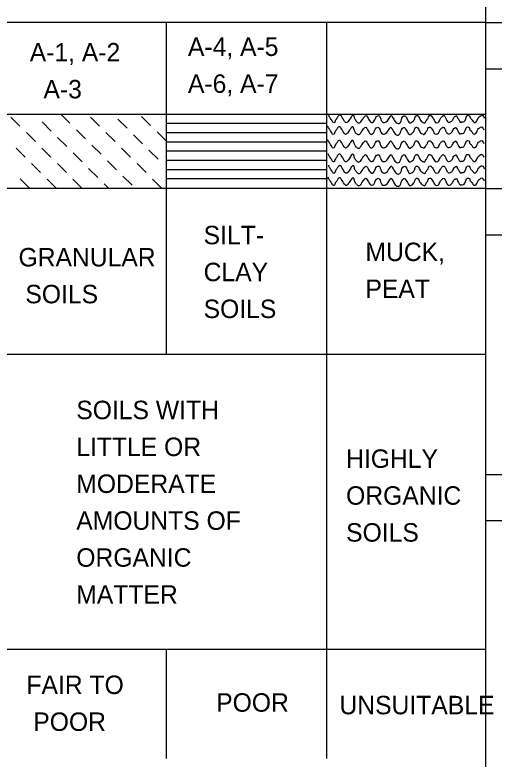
# Model space of a CAD drawing. Extents: x 278710 to 279187, y 171464 to 171625.
# Drawn here: x 279032.01 to 279043.27, y 171537.43 to 171554.93 of the extents above; entities that cross this region are included whole.
import ezdxf

# ---------------------------------------------------------------- set-up
doc = ezdxf.new("R2010")
doc.units = 0
doc.layers.add('Prop Strc Sect_ Misc - User Comment (Tx - small)', color=7, linetype='Continuous')

msp = doc.modelspace()

# ---------------------------------------------------------------- linework, layer by layer
at = {"layer": 'Prop Strc Sect_ Misc - User Comment (Tx - small)'}
for p, q in [((279043.07, 171566.02), (279043.07, 171485.806)), ((279005.33, 171554.763), (279043.07, 171554.763)), ((279035.566, 171546.942), (279035.566, 171554.737)), ((279039.34, 171537.446), (279039.34, 171554.763)), ((279081.678, 171554.741), (279043.07, 171554.741)), ((279081.678, 171553.657), (279043.07, 171553.657)), ((279005.33, 171552.594), (279043.07, 171552.594)), ((279032.125, 171552.316), (279031.913, 171552.529)), ((279033.089, 171552.594), (279033.301, 171552.382)), ((279033.995, 171552.316), (279033.783, 171552.529)), ((279034.429, 171552.477), (279034.642, 171552.264)), ((279035.197, 171552.329), (279034.984, 171552.542)), ((279032.859, 171552.199), (279032.646, 171552.412)), ((279035.566, 171552.382), (279039.34, 171552.382)), ((279039.366, 171552.312), (279039.361, 171552.308)), ((279032.49, 171551.952), (279032.277, 171552.165)), ((279033.453, 171552.23), (279033.665, 171552.017)), ((279034.36, 171551.952), (279034.147, 171552.165)), ((279034.793, 171552.113), (279035.006, 171551.9)), ((279035.561, 171551.965), (279035.349, 171552.178)), ((279035.566, 171552.165), (279039.34, 171552.165)), ((279033.223, 171551.835), (279033.01, 171552.048)), ((279035.566, 171551.948), (279039.34, 171551.948)), ((279039.366, 171551.991), (279039.361, 171551.987)), ((279032.247, 171551.588), (279032.034, 171551.8)), ((279032.854, 171551.588), (279032.642, 171551.8)), ((279033.817, 171551.865), (279034.03, 171551.653)), ((279034.724, 171551.588), (279034.511, 171551.8)), ((279035.158, 171551.748), (279035.37, 171551.536)), ((279033.375, 171551.683), (279033.587, 171551.471)), ((279035.566, 171551.731), (279039.34, 171551.731)), ((279039.37, 171551.666), (279039.366, 171551.661)), ((279032.611, 171551.223), (279032.399, 171551.436)), ((279033.219, 171551.223), (279033.006, 171551.436)), ((279034.182, 171551.501), (279034.394, 171551.288)), ((279035.088, 171551.223), (279034.876, 171551.436)), ((279035.566, 171551.514), (279039.34, 171551.514)), ((279039.379, 171551.397), (279039.374, 171551.392)), ((279033.739, 171551.319), (279033.952, 171551.106)), ((279035.566, 171551.297), (279039.34, 171551.297)), ((279032.342, 171550.863), (279032.13, 171551.076)), ((279032.976, 171550.859), (279032.763, 171551.071)), ((279033.583, 171550.859), (279033.37, 171551.071)), ((279034.546, 171551.137), (279034.759, 171550.924)), ((279035.453, 171550.859), (279035.24, 171551.071)), ((279035.566, 171551.08), (279039.34, 171551.08)), ((279039.348, 171551.08), (279039.344, 171551.076)), ((279039.374, 171551.111), (279039.37, 171551.106)), ((279034.104, 171550.954), (279034.203, 171550.859)), ((279039.344, 171551.037), (279039.34, 171551.041)), ((279005.33, 171550.859), (279043.07, 171550.859)), ((279081.678, 171550.837), (279043.07, 171550.837)), ((279081.678, 171549.753), (279043.07, 171549.753)), ((279005.33, 171546.955), (279043.07, 171546.955)), ((279081.678, 171544.113), (279043.07, 171544.113)), ((279079.076, 171544.113), (279043.07, 171544.113)), ((279081.678, 171543.029), (279043.07, 171543.029)), ((279005.33, 171540.014), (279043.07, 171540.014)), ((279035.566, 171537.446), (279035.566, 171540.001))]:
    msp.add_line(p, q, dxfattribs=at)
for points in [[(279040.042, 171552.416), (279040.016, 171552.451), (279039.986, 171552.525), (279039.969, 171552.568), (279039.951, 171552.572), (279039.93, 171552.559), (279039.899, 171552.512), (279039.838, 171552.425), (279039.817, 171552.403), (279039.791, 171552.395), (279039.773, 171552.403), (279039.756, 171552.425), (279039.682, 171552.546), (279039.665, 171552.568), (279039.656, 171552.572), (279039.635, 171552.572), (279039.609, 171552.555), (279039.574, 171552.499), (279039.53, 171552.425), (279039.526, 171552.403), (279039.5, 171552.395), (279039.478, 171552.408), (279039.465, 171552.434), (279039.413, 171552.512), (279039.374, 171552.581)], [(279040.047, 171552.416), (279040.077, 171552.39), (279040.138, 171552.412), (279040.168, 171552.46), (279040.229, 171552.542), (279040.255, 171552.564), (279040.29, 171552.529), (279040.32, 171552.477), (279040.355, 171552.425), (279040.389, 171552.399), (279040.433, 171552.412), (279040.467, 171552.464), (279040.533, 171552.559), (279040.567, 171552.559), (279040.593, 171552.516), (279040.663, 171552.403), (279040.697, 171552.399), (279040.732, 171552.412), (279040.832, 171552.542), (279040.858, 171552.564), (279040.871, 171552.542), (279040.897, 171552.503), (279040.949, 171552.412), (279041.036, 171552.377), (279041.066, 171552.403), (279041.127, 171552.538), (279041.175, 171552.559), (279041.192, 171552.538), (279041.253, 171552.434), (279041.287, 171552.39), (279041.344, 171552.412), (279041.404, 171552.486), (279041.439, 171552.559), (279041.47, 171552.564), (279041.504, 171552.525), (279041.556, 171552.434), (279041.604, 171552.403), (279041.634, 171552.39), (279041.678, 171552.447), (279041.717, 171552.503), (279041.743, 171552.559), (279041.782, 171552.564), (279041.804, 171552.542), (279041.86, 171552.451), (279041.895, 171552.403), (279041.955, 171552.403), (279042.007, 171552.49), (279042.06, 171552.551), (279042.077, 171552.564), (279042.12, 171552.529), (279042.151, 171552.464), (279042.203, 171552.403), (279042.246, 171552.412), (279042.298, 171552.46), (279042.35, 171552.542), (279042.372, 171552.551), (279042.385, 171552.559), (279042.402, 171552.529), (279042.424, 171552.49), (279042.493, 171552.403), (279042.511, 171552.412), (279042.541, 171552.412), (279042.615, 171552.525), (279042.641, 171552.564), (279042.693, 171552.559), (279042.706, 171552.516), (279042.754, 171552.46), (279042.801, 171552.403), (279042.832, 171552.403), (279042.866, 171552.438), (279042.897, 171552.512)], [(279042.897, 171552.512), (279042.944, 171552.551), (279042.984, 171552.572), (279043.018, 171552.542), (279043.044, 171552.503)], [(279040.029, 171552.143), (279040.003, 171552.178), (279039.973, 171552.251), (279039.956, 171552.295), (279039.938, 171552.299), (279039.917, 171552.286), (279039.886, 171552.238), (279039.825, 171552.152), (279039.804, 171552.13), (279039.778, 171552.121), (279039.76, 171552.13), (279039.743, 171552.152), (279039.669, 171552.273), (279039.652, 171552.295), (279039.643, 171552.299), (279039.622, 171552.299), (279039.596, 171552.282), (279039.561, 171552.225), (279039.517, 171552.152), (279039.513, 171552.13), (279039.487, 171552.121), (279039.465, 171552.134), (279039.452, 171552.16), (279039.4, 171552.238), (279039.361, 171552.308)], [(279040.034, 171552.143), (279040.064, 171552.117), (279040.125, 171552.139), (279040.155, 171552.186), (279040.216, 171552.269), (279040.242, 171552.29), (279040.277, 171552.256), (279040.307, 171552.204), (279040.342, 171552.152), (279040.376, 171552.126), (279040.42, 171552.139), (279040.454, 171552.191), (279040.52, 171552.286), (279040.554, 171552.286), (279040.58, 171552.243), (279040.65, 171552.13), (279040.684, 171552.126), (279040.719, 171552.139), (279040.819, 171552.269), (279040.845, 171552.29), (279040.858, 171552.269), (279040.884, 171552.23), (279040.936, 171552.139), (279041.023, 171552.104), (279041.053, 171552.13), (279041.114, 171552.264), (279041.162, 171552.286), (279041.179, 171552.264), (279041.24, 171552.16), (279041.274, 171552.117), (279041.331, 171552.139), (279041.391, 171552.212), (279041.426, 171552.286), (279041.457, 171552.29), (279041.491, 171552.251), (279041.543, 171552.16), (279041.591, 171552.13), (279041.621, 171552.117), (279041.665, 171552.173), (279041.704, 171552.23), (279041.73, 171552.286), (279041.769, 171552.29), (279041.791, 171552.269), (279041.847, 171552.178), (279041.882, 171552.13), (279041.942, 171552.13), (279041.994, 171552.217), (279042.046, 171552.277), (279042.064, 171552.29), (279042.107, 171552.256), (279042.138, 171552.191), (279042.19, 171552.13), (279042.233, 171552.139), (279042.285, 171552.186), (279042.337, 171552.269), (279042.359, 171552.277), (279042.372, 171552.286), (279042.389, 171552.256), (279042.411, 171552.217), (279042.48, 171552.13), (279042.498, 171552.139), (279042.528, 171552.139), (279042.602, 171552.251), (279042.628, 171552.29), (279042.68, 171552.286), (279042.693, 171552.243), (279042.741, 171552.186), (279042.788, 171552.13), (279042.819, 171552.13), (279042.853, 171552.165), (279042.884, 171552.238)], [(279042.884, 171552.238), (279042.931, 171552.277), (279042.97, 171552.299), (279043.005, 171552.269), (279043.031, 171552.23)], [(279040.029, 171551.822), (279040.003, 171551.857), (279039.973, 171551.93), (279039.956, 171551.974), (279039.938, 171551.978), (279039.917, 171551.965), (279039.886, 171551.917), (279039.825, 171551.831), (279039.804, 171551.809), (279039.778, 171551.8), (279039.76, 171551.809), (279039.743, 171551.831), (279039.669, 171551.952), (279039.652, 171551.974), (279039.643, 171551.978), (279039.622, 171551.978), (279039.596, 171551.961), (279039.561, 171551.904), (279039.517, 171551.831), (279039.513, 171551.809), (279039.487, 171551.8), (279039.465, 171551.813), (279039.452, 171551.839), (279039.4, 171551.917), (279039.361, 171551.987)], [(279040.034, 171551.822), (279040.064, 171551.796), (279040.125, 171551.818), (279040.155, 171551.865), (279040.216, 171551.948), (279040.242, 171551.969), (279040.277, 171551.935), (279040.307, 171551.883), (279040.342, 171551.831), (279040.376, 171551.805), (279040.42, 171551.818), (279040.454, 171551.87), (279040.52, 171551.965), (279040.554, 171551.965), (279040.58, 171551.922), (279040.65, 171551.809), (279040.684, 171551.805), (279040.719, 171551.818), (279040.819, 171551.948), (279040.845, 171551.969), (279040.858, 171551.948), (279040.884, 171551.909), (279040.936, 171551.818), (279041.023, 171551.783), (279041.053, 171551.809), (279041.114, 171551.943), (279041.162, 171551.965), (279041.179, 171551.943), (279041.24, 171551.839), (279041.274, 171551.796), (279041.331, 171551.818), (279041.391, 171551.891), (279041.426, 171551.965), (279041.457, 171551.969), (279041.491, 171551.93), (279041.543, 171551.839), (279041.591, 171551.809), (279041.621, 171551.796), (279041.665, 171551.852), (279041.704, 171551.909), (279041.73, 171551.965), (279041.769, 171551.969), (279041.791, 171551.948), (279041.847, 171551.857), (279041.882, 171551.809), (279041.942, 171551.809), (279041.994, 171551.896), (279042.046, 171551.956), (279042.064, 171551.969), (279042.107, 171551.935), (279042.138, 171551.87), (279042.19, 171551.809), (279042.233, 171551.818), (279042.285, 171551.865), (279042.337, 171551.948), (279042.359, 171551.956), (279042.372, 171551.965), (279042.389, 171551.935), (279042.411, 171551.896), (279042.48, 171551.809), (279042.498, 171551.818), (279042.528, 171551.818), (279042.602, 171551.93), (279042.628, 171551.969), (279042.68, 171551.965), (279042.693, 171551.922), (279042.741, 171551.865), (279042.788, 171551.809), (279042.819, 171551.809), (279042.853, 171551.844), (279042.884, 171551.917)], [(279042.884, 171551.917), (279042.931, 171551.956), (279042.97, 171551.978), (279043.005, 171551.948), (279043.031, 171551.909)], [(279040.034, 171551.497), (279040.008, 171551.531), (279039.977, 171551.605), (279039.96, 171551.648), (279039.943, 171551.653), (279039.921, 171551.64), (279039.891, 171551.592), (279039.83, 171551.505), (279039.808, 171551.484), (279039.782, 171551.475), (279039.765, 171551.484), (279039.747, 171551.505), (279039.674, 171551.627), (279039.656, 171551.648), (279039.648, 171551.653), (279039.626, 171551.653), (279039.6, 171551.635), (279039.565, 171551.579), (279039.522, 171551.505), (279039.517, 171551.484), (279039.491, 171551.475), (279039.47, 171551.488), (279039.457, 171551.514), (279039.405, 171551.592), (279039.366, 171551.661)], [(279040.038, 171551.497), (279040.068, 171551.471), (279040.129, 171551.492), (279040.159, 171551.54), (279040.22, 171551.622), (279040.246, 171551.644), (279040.281, 171551.609), (279040.311, 171551.557), (279040.346, 171551.505), (279040.381, 171551.479), (279040.424, 171551.492), (279040.459, 171551.544), (279040.524, 171551.64), (279040.559, 171551.64), (279040.585, 171551.596), (279040.654, 171551.484), (279040.689, 171551.479), (279040.723, 171551.492), (279040.823, 171551.622), (279040.849, 171551.644), (279040.862, 171551.622), (279040.888, 171551.583), (279040.94, 171551.492), (279041.027, 171551.458), (279041.057, 171551.484), (279041.118, 171551.618), (279041.166, 171551.64), (279041.183, 171551.618), (279041.244, 171551.514), (279041.279, 171551.471), (279041.335, 171551.492), (279041.396, 171551.566), (279041.431, 171551.64), (279041.461, 171551.644), (279041.496, 171551.605), (279041.548, 171551.514), (279041.595, 171551.484), (279041.626, 171551.471), (279041.669, 171551.527), (279041.708, 171551.583), (279041.734, 171551.64), (279041.773, 171551.644), (279041.795, 171551.622), (279041.851, 171551.531), (279041.886, 171551.484), (279041.947, 171551.484), (279041.999, 171551.57), (279042.051, 171551.631), (279042.068, 171551.644), (279042.112, 171551.609), (279042.142, 171551.544), (279042.194, 171551.484), (279042.237, 171551.492), (279042.289, 171551.54), (279042.341, 171551.622), (279042.363, 171551.631), (279042.376, 171551.64), (279042.394, 171551.609), (279042.415, 171551.57), (279042.485, 171551.484), (279042.502, 171551.492), (279042.532, 171551.492), (279042.606, 171551.605), (279042.632, 171551.644), (279042.684, 171551.64), (279042.697, 171551.596), (279042.745, 171551.54), (279042.793, 171551.484), (279042.823, 171551.484), (279042.858, 171551.518), (279042.888, 171551.592)], [(279042.888, 171551.592), (279042.936, 171551.631), (279042.975, 171551.653), (279043.01, 171551.622), (279043.036, 171551.583)], [(279040.042, 171551.228), (279040.016, 171551.262), (279039.986, 171551.336), (279039.969, 171551.379), (279039.951, 171551.384), (279039.93, 171551.371), (279039.899, 171551.323), (279039.838, 171551.236), (279039.817, 171551.215), (279039.791, 171551.206), (279039.773, 171551.215), (279039.756, 171551.236), (279039.682, 171551.358), (279039.665, 171551.379), (279039.656, 171551.384), (279039.635, 171551.384), (279039.609, 171551.366), (279039.574, 171551.31), (279039.53, 171551.236), (279039.526, 171551.215), (279039.5, 171551.206), (279039.478, 171551.219), (279039.465, 171551.245), (279039.413, 171551.323), (279039.374, 171551.392)], [(279040.047, 171551.228), (279040.077, 171551.202), (279040.138, 171551.223), (279040.168, 171551.271), (279040.229, 171551.353), (279040.255, 171551.375), (279040.29, 171551.34), (279040.32, 171551.288), (279040.355, 171551.236), (279040.389, 171551.21), (279040.433, 171551.223), (279040.467, 171551.275), (279040.533, 171551.371), (279040.567, 171551.371), (279040.593, 171551.327), (279040.663, 171551.215), (279040.697, 171551.21), (279040.732, 171551.223), (279040.832, 171551.353), (279040.858, 171551.375), (279040.871, 171551.353), (279040.897, 171551.314), (279040.949, 171551.223), (279041.036, 171551.189), (279041.066, 171551.215), (279041.127, 171551.349), (279041.175, 171551.371), (279041.192, 171551.349), (279041.253, 171551.245), (279041.287, 171551.202), (279041.344, 171551.223), (279041.404, 171551.297), (279041.439, 171551.371), (279041.47, 171551.375), (279041.504, 171551.336), (279041.556, 171551.245), (279041.604, 171551.215), (279041.634, 171551.202), (279041.678, 171551.258), (279041.717, 171551.314), (279041.743, 171551.371), (279041.782, 171551.375), (279041.804, 171551.353), (279041.86, 171551.262), (279041.895, 171551.215), (279041.955, 171551.215), (279042.007, 171551.301), (279042.06, 171551.362), (279042.077, 171551.375), (279042.12, 171551.34), (279042.151, 171551.275), (279042.203, 171551.215), (279042.246, 171551.223), (279042.298, 171551.271), (279042.35, 171551.353), (279042.372, 171551.362), (279042.385, 171551.371), (279042.402, 171551.34), (279042.424, 171551.301), (279042.493, 171551.215), (279042.511, 171551.223), (279042.541, 171551.223), (279042.615, 171551.336), (279042.641, 171551.375), (279042.693, 171551.371), (279042.706, 171551.327), (279042.754, 171551.271), (279042.801, 171551.215), (279042.832, 171551.215), (279042.866, 171551.249), (279042.897, 171551.323)], [(279042.897, 171551.323), (279042.944, 171551.362), (279042.984, 171551.384), (279043.018, 171551.353), (279043.044, 171551.314)], [(279040.038, 171550.941), (279040.012, 171550.976), (279039.982, 171551.05), (279039.964, 171551.093), (279039.947, 171551.097), (279039.925, 171551.084), (279039.895, 171551.037), (279039.834, 171550.95), (279039.812, 171550.928), (279039.786, 171550.92), (279039.769, 171550.928), (279039.752, 171550.95), (279039.678, 171551.071), (279039.661, 171551.093), (279039.652, 171551.097), (279039.63, 171551.097), (279039.604, 171551.08), (279039.57, 171551.024), (279039.526, 171550.95), (279039.522, 171550.928), (279039.496, 171550.92), (279039.474, 171550.933), (279039.461, 171550.959), (279039.409, 171551.037), (279039.37, 171551.106)], [(279040.042, 171550.941), (279040.073, 171550.915), (279040.133, 171550.937), (279040.164, 171550.985), (279040.225, 171551.067), (279040.251, 171551.089), (279040.285, 171551.054), (279040.316, 171551.002), (279040.35, 171550.95), (279040.385, 171550.924), (279040.428, 171550.937), (279040.463, 171550.989), (279040.528, 171551.084), (279040.563, 171551.084), (279040.589, 171551.041), (279040.658, 171550.928), (279040.693, 171550.924), (279040.728, 171550.937), (279040.828, 171551.067), (279040.854, 171551.089), (279040.867, 171551.067), (279040.893, 171551.028), (279040.945, 171550.937), (279041.031, 171550.902), (279041.062, 171550.928), (279041.123, 171551.063), (279041.17, 171551.084), (279041.188, 171551.063), (279041.248, 171550.959), (279041.283, 171550.915), (279041.339, 171550.937), (279041.4, 171551.011), (279041.435, 171551.084), (279041.465, 171551.089), (279041.5, 171551.05), (279041.552, 171550.959), (279041.6, 171550.928), (279041.63, 171550.915), (279041.673, 171550.972), (279041.712, 171551.028), (279041.739, 171551.084), (279041.778, 171551.089), (279041.799, 171551.067), (279041.856, 171550.976), (279041.89, 171550.928), (279041.951, 171550.928), (279042.003, 171551.015), (279042.055, 171551.076), (279042.073, 171551.089), (279042.116, 171551.054), (279042.146, 171550.989), (279042.198, 171550.928), (279042.242, 171550.937), (279042.294, 171550.985), (279042.346, 171551.067), (279042.368, 171551.076), (279042.381, 171551.084), (279042.398, 171551.054), (279042.42, 171551.015), (279042.489, 171550.928), (279042.506, 171550.937), (279042.537, 171550.937), (279042.61, 171551.05), (279042.636, 171551.089), (279042.689, 171551.084), (279042.702, 171551.041), (279042.749, 171550.985), (279042.797, 171550.928), (279042.827, 171550.928), (279042.862, 171550.963), (279042.892, 171551.037)], [(279042.892, 171551.037), (279042.94, 171551.076), (279042.979, 171551.097), (279043.014, 171551.067), (279043.04, 171551.028)]]:
    msp.add_spline(points, degree=3, dxfattribs=at)

# ---------------------------------------------------------------- texts
for s, p in [('A-4, A-5', (279036.073, 171553.965)), ('A-1, A-2', (279032.355, 171553.835)), ('A-6, A-7', (279036.073, 171553.097)), ('  A-3', (279032.355, 171552.967)), ('SILT-', (279036.442, 171549.536)), ('MUCK,', (279040.246, 171549.141)), ('GRANULAR', (279032.091, 171549.015)), ('CLAY', (279036.442, 171548.668)), ('PEAT', (279040.246, 171548.273)), (' SOILS', (279032.091, 171548.148)), ('SOILS', (279036.442, 171547.801)), ('SOILS WITH', (279033.449, 171545.423)), ('LITTLE OR', (279033.449, 171544.556)), ('HIGHLY', (279039.791, 171544.278)), ('MODERATE', (279033.449, 171543.688)), ('ORGANIC', (279039.791, 171543.411)), ('AMOUNTS OF', (279033.449, 171542.821)), ('SOILS', (279039.791, 171542.543)), ('ORGANIC', (279033.449, 171541.953)), ('MATTER', (279033.449, 171541.085)), ('FAIR TO', (279032.277, 171538.96)), ('POOR', (279036.737, 171538.543)), ('UNSUITABLE', (279039.635, 171538.483)), (' POOR', (279032.277, 171538.092))]:
    msp.add_text(s, height=0.4338, dxfattribs=at).set_placement(p)

doc.saveas('drawing.dxf')
